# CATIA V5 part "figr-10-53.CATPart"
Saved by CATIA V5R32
Part number: Part1
Bounding box of the stored display mesh (mm): x 0 to 100, y -43.492 to 31.468, z -3.623 to 11.497
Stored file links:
  D:\PROJECTS\Project 2022\CATIA V5 6R 2022\Resources\Part Files\c10_catia_v5_6r2022_prt\c10_catia_v5_6r2022_prt\figr-10-53.CATPart
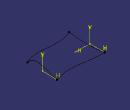
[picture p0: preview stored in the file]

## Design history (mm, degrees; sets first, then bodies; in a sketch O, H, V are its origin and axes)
Set1
  Sketch1 on yz-plane, origin (0, 0, 0), H (0, 1, 0), V (0, 0, 1)
  Plane1: type Offset, RefPlane yz-plane, Offset 100
  Sketch2 on xy-plane, origin (0, 0, 0), H (1, 0, 0), V (0, 1, 0)
    spline S1 through (0, 31.0443) (19.7053, 31.0443) (51.809, 26.4574) (100, 31.0443)
    reference intersected line E1 through (100, 0) direction (0, 1) from Plane1
    point P1 (0, 31.0443)
    point P2 (100, 31.0443)
    coincidence: P1 V, P2 E1
  Sketch3 on xy-plane, origin (0, 0, 0), H (1, 0, 0), V (0, 1, 0)
    spline S1 through (0, -43.492) (26.209, -36.2295) (80.3728, -38.1407) (100, -32.0249)
    reference intersected line E1 through (100, 0) direction (0, 1) from Plane1
    point P1 (0, -43.492)
    point P2 (100, -32.0249)
    coincidence: P1 V, P2 E1
  Sketch4 on Plane1, origin (100, 0, 0), H (0, 1, 0), V (0, 0, 1)
    spline S1 through (-32.0249, 0) (-14.5305, 11.3827) (11.9668, 5.3652) (31.0443, 0)
    reference projected point E1 (31.0443, 0) from vertex of Sketch2
    reference projected point E2 (-32.0249, 0) from vertex of Sketch3
    point P1 (-32.0249, 0)
    point P2 (31.0443, 0)
    coincidence: P1 H, P2 H, P2 E1, P1 E2
  Sketch5 on yz-plane, origin (0, 0, 0), H (0, 1, 0), V (0, 0, 1)
    spline S1 through (31.0443, 0) (7.4727, -3.1675) (-43.492, 0)
    reference projected point E1 (-43.492, 0) from vertex of Sketch3
    reference projected point E2 (31.0443, 0) from vertex of Sketch2
    point P1 (31.0443, 0)
    point P2 (-43.492, 0)
    coincidence: P1 H, P2 H, P2 E1, P1 E2
Body1 (main body)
